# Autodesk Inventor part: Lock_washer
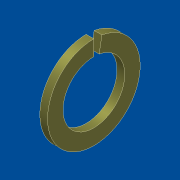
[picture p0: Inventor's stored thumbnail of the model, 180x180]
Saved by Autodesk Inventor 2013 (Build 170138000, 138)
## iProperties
Shininess: 25.0
Length Units: 11269
Angle Units: 11279
Time Units: 11290
Mass Units: 11283
Length Display Precision: 3
Angle Display Precision: 2
Created: 2001-04
Part Number: Lock_washer
Material: Standard
Document SubType Name: Modellieren
Designer: dl
Density: 1 g/cm^3
Density: 0.0
Volumn: 0.0
Area: 0.0
PropertySet Name: Model Information
Control State: 0
Master: False
Checked Out: False
Author: dl
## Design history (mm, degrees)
body "Solid1"
revolve "Revolution1" stored, may be unused: angle "d3" = 350 deg
sketch "Sketch1"
  geometry: L1 (-19.342, 6.402)-(-19.842, 6.402); L2 (-19.842, 6.402)-(-19.842, 7.402); L3 (-19.842, 7.402)-(-19.342, 7.402); L4 (-19.342, 7.402)-(-19.342, 6.402); L5 (-20.189, 4.402)-(-18.803, 4.402)
  constraints: 10 end point, 2 parallel, 2 perpendicular, 1 horizontal
  dimensions: "d0" = 0.5 distance of L2.end L3.end; "d1" = 1 distance of L3.end L1.start; "d2" = 2 distance from line of L5 L1.end
